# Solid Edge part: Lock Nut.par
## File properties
Author: Sarvanan
Template: sync iso part.par
Last saved by: Cadcim
Revision: 4
Application: Solid Edge
Accuracy: 0.990
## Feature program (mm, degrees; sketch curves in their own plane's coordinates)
sketch for "Hole_1" plane through (21.0838, 43.6973, 8) normal (0, 0, 1) x-axis (1, 0, 0)
  hole centre (-1.3414, 0.2221) bore radius 6
hole "Hole_1" diameter 12 through
pattern "unnamed Pattern 1" of "Hole_1"
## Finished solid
Body 1: solid body, 21 faces, 56 edges, 36 vertices.
  Faces by surface: spun 12, plane 8, cylinder 1
  Edges by curve: circle 21, line 18, intersection 17
Bounding box of the edges (mm; curved faces can reach further): 30.022 x 26.000 x 8.000, from (4.7313, 30.9194, 0) to (34.7535, 56.9194, 8).
Cylindrical faces by radius (mm): R6 x1
Planar faces by outward normal: +y 1, +z 1, -y 1, -z 1, oblique 4
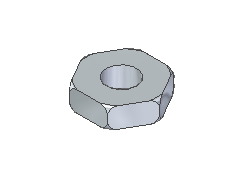
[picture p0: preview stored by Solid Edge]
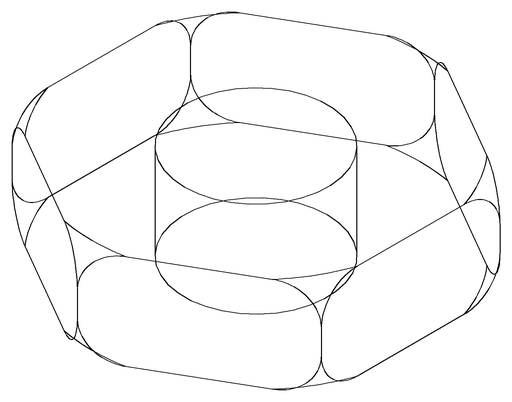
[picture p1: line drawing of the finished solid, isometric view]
